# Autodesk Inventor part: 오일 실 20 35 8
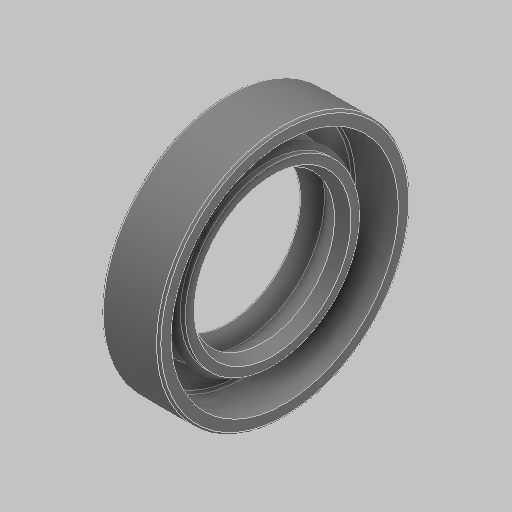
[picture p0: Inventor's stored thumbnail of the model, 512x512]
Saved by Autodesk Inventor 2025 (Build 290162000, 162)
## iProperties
Created: 2024-08
Part Number: 오일 실 20 35 8
Material: 고무
Description: 오일-실
Document SubType Name: Modeling
Designer: 현기
Density: 0.93 g/cm^3
Appearance: 기본값
Author: jhkim
Sending System: Autodesk Inventor 2025
Preprocessor: ST-DEVELOPER v20
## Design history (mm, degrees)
feature "Solid1"
node "솔리드1"
